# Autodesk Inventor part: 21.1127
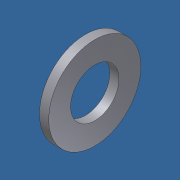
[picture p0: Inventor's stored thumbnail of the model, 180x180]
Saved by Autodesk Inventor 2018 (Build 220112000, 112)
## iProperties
Created: 2006-02
Part Number: 21.1127
Material: Steel, Mild
Description: M8 ROUND WASHER
Document SubType Name: Modeling
Standard: DIN 125
Designer: Andy Moles
Standards Organization: DIN
Language: en-US
Size Designation: A 8.4
Categories: <MemberInstance><Categories><Category DisplayName="Fasteners" InternalName="e4da775c-781d-43d5-af7c-5136215cf5a6" Mnemonic="FSTN"><Category DisplayName="Washers
Mass: 1.82929 g
Surface Area: 4.13936 cm^2
Volume: 0.233031 cm^3
Density: 7.85 g/cm^3
Vendor: S
Appearance: Zinc
Author: Andy Moles
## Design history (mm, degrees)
sketch "Sketch"
  geometry: C1 r 8 at (0, 0); C2 r 4.2 at (0, 0); 1 further point
  constraints: 2 centre point, 2 coincident
  dimensions: "d0" = 8.4 diameter of C2 (= SD1); "d1" = 16 diameter of C1 (= SD2)
extrude "Body" new body sketch "Sketch" distance "d2" = 1.6 (= SD); taper "d3" = 0 deg
workaxis "Work Axis1"
workplane "Work Plane1"
body "Solid1"
other parameters: "SD1" = 8.4 [user parameter; used in 1 equation term], "SD2" = 16 [user parameter; used in 1 equation term], "SD" = 1.6 [user parameter; used in 1 equation term], "d4" = 0, "d5" = 0, "d6" = 0, "d7" = 0, "NND" = 8 [user parameter]
